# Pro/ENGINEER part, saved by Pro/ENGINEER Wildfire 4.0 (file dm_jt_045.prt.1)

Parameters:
  METRIC = "NO"

Other parameters: PITCH, DRILL_POINT_ANGLE, DRILL_DEPTH, DRILL_DIAMETER, THREAD_DIAMETER, THREADS_PER_INCH, THREAD_DEPTH, THREAD_LENGTH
